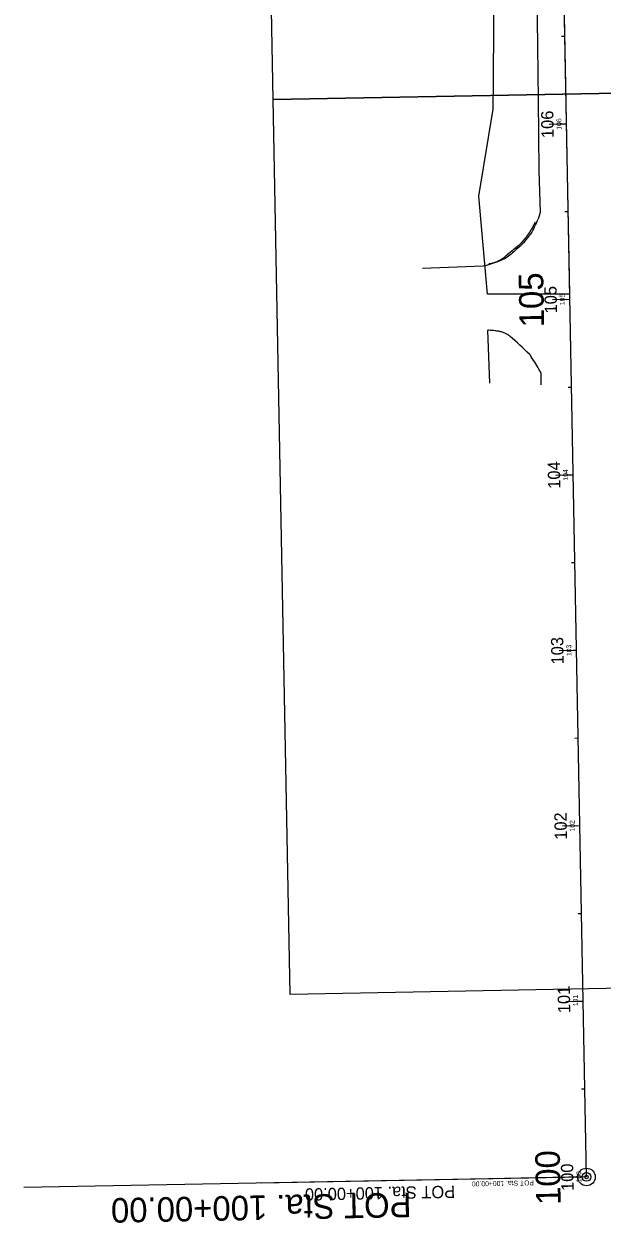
# Model space of a CAD drawing. Extents: x 2287043 to 2296348, y 637947 to 641293.
# Drawn here: x 2287081 to 2287410, y 637947 to 638630 of the extents above; entities that cross this region are included whole.
import ezdxf

# ---------------------------------------------------------------- set-up
doc = ezdxf.new("R2010")
doc.units = 0
for name, color, linetype in [('DR_P_Drainage_Area', 7, 'Continuous'), ('GE_X_CL_100', 7, 'Continuous'), ('GE_X_CL_20', 7, 'Continuous'), ('GE_X_CL_50', 7, 'Continuous'), ('SC_Scratch2', 7, 'Continuous'), ('SC_Scratch4', 7, 'Continuous')]:
    doc.layers.add(name, color=color, linetype=linetype)

msp = doc.modelspace()

# ---------------------------------------------------------------- linework, layer by layer
at = {"layer": 'DR_P_Drainage_Area'}
msp.add_line((2287391.95, 638476.45), (2287345.11, 638476.45), dxfattribs=at)
for points in [[(2287365.99, 639861.68), (2287378.81, 639153.12), (2287391.95, 638476.45)], [(2287345.11, 638476.45), (2287340.17, 638532.29), (2287348.41, 638581.77), (2287348.51, 638598.52), (2287348.89, 638659.2), (2287344.64, 638715.18), (2287332.07, 638761.85), (2287327.5, 638851.7)]]:
    msp.add_lwpolyline(points, dxfattribs=at)
at = {"layer": 'GE_X_CL_100'}
for p, q in [((2287401.6, 637973.38), (2287357.08, 640335.42)), ((2287390.29, 638573.28), (2287380.3, 638573.09)), ((2287392.18, 638473.29), (2287382.18, 638473.1)), ((2287394.06, 638373.31), (2287384.06, 638373.12)), ((2287395.95, 638273.33), (2287385.95, 638273.14)), ((2287397.83, 638173.35), (2287387.83, 638173.16)), ((2287399.72, 638073.36), (2287389.72, 638073.18)), ((2287396.6, 637973.29), (2287081.17, 637967.34)), ((2287401.6, 637973.38), (2287391.6, 637973.19))]:
    msp.add_line(p, q, dxfattribs=at)
msp.add_circle((2287401.6, 637973.38), 5, dxfattribs=at)
at = {"layer": 'GE_X_CL_20'}
for p, q in [((2287401.6, 637973.38), (2287357.08, 640335.42)), ((2287389.35, 638623.27), (2287387.35, 638623.23)), ((2287390.29, 638573.28), (2287388.29, 638573.24)), ((2287391.24, 638523.28), (2287389.24, 638523.25)), ((2287392.18, 638473.29), (2287390.18, 638473.26)), ((2287393.12, 638423.3), (2287391.12, 638423.26)), ((2287394.06, 638373.31), (2287392.06, 638373.27)), ((2287395.01, 638323.32), (2287393.01, 638323.28)), ((2287395.95, 638273.33), (2287393.95, 638273.29)), ((2287396.89, 638223.34), (2287394.89, 638223.3)), ((2287397.83, 638173.35), (2287395.83, 638173.31)), ((2287398.77, 638123.36), (2287396.77, 638123.32)), ((2287399.72, 638073.36), (2287397.72, 638073.33)), ((2287400.66, 638023.37), (2287398.66, 638023.34)), ((2287400.6, 637973.36), (2287327.52, 637971.99)), ((2287401.6, 637973.38), (2287399.6, 637973.34))]:
    msp.add_line(p, q, dxfattribs=at)
msp.add_circle((2287401.6, 637973.38), 1, dxfattribs=at)
at = {"layer": 'GE_X_CL_50'}
for p, q in [((2287401.6, 637973.38), (2287357.08, 640335.42)), ((2287390.29, 638573.28), (2287385.3, 638573.18)), ((2287390.29, 638573.28), (2287385.3, 638573.18)), ((2287392.18, 638473.29), (2287387.18, 638473.2)), ((2287392.18, 638473.29), (2287387.18, 638473.2)), ((2287394.06, 638373.31), (2287389.06, 638373.22)), ((2287394.06, 638373.31), (2287389.06, 638373.22)), ((2287395.95, 638273.33), (2287390.95, 638273.23)), ((2287395.95, 638273.33), (2287390.95, 638273.23)), ((2287397.83, 638173.35), (2287392.83, 638173.25)), ((2287397.83, 638173.35), (2287392.83, 638173.25)), ((2287399.72, 638073.36), (2287394.72, 638073.27)), ((2287399.72, 638073.36), (2287394.72, 638073.27)), ((2287399.1, 637973.33), (2287216.39, 637969.89)), ((2287399.1, 637973.33), (2287216.39, 637969.89)), ((2287401.6, 637973.38), (2287396.6, 637973.29)), ((2287401.6, 637973.38), (2287396.6, 637973.29))]:
    msp.add_line(p, q, dxfattribs=at)
msp.add_circle((2287401.6, 637973.38), 2.5, dxfattribs=at)
msp.add_circle((2287401.6, 637973.38), 2.5, dxfattribs=at)
at = {"layer": 'SC_Scratch2'}
for points in [[(2287223.14, 638587.24), (2287213.53, 639097.15), (2287543.47, 639103.37), (2287553.08, 638593.46)], [(2287232.75, 638077.33), (2287223.14, 638587.24), (2287553.08, 638593.46), (2287562.69, 638083.55)]]:
    msp.add_lwpolyline(points, close=True, dxfattribs=at)
at = {"layer": 'SC_Scratch4'}
for p, q in [((2287375.16, 638522.93), (2287373.97, 638519.1)), ((2287369.14, 638510.1), (2287365.74, 638505.65)), ((2287369.57, 638510.68), (2287369.14, 638510.1)), ((2287369.57, 638510.68), (2287369.88, 638510.55)), ((2287342.63, 638492.34), (2287308.17, 638491.1)), ((2287346.59, 638425.74), (2287345.42, 638455.81)), ((2287369.52, 638441.89), (2287369.24, 638442.1)), ((2287369.52, 638441.89), (2287370.03, 638440.47)), ((2287374.96, 638432.68), (2287375.56, 638431.4))]:
    msp.add_line(p, q, dxfattribs=at)
for points in [[(2287371.95, 638767.2), (2287373.28, 638718.62), (2287373.47, 638673.87), (2287373.54, 638632.64), (2287374, 638587.11), (2287374.45, 638546.92), (2287375.16, 638522.93)], [(2287372.28, 638517.32), (2287372.2, 638517.16), (2287372.12, 638516.99), (2287372.04, 638516.83), (2287371.96, 638516.66), (2287371.87, 638516.5), (2287371.79, 638516.33), (2287371.71, 638516.17), (2287371.62, 638516.01), (2287371.54, 638515.84), (2287371.45, 638515.68), (2287371.37, 638515.52), (2287371.28, 638515.36), (2287371.19, 638515.19), (2287371.1, 638515.03), (2287371.02, 638514.87), (2287370.93, 638514.71), (2287370.84, 638514.55), (2287370.75, 638514.39), (2287370.66, 638514.23), (2287370.56, 638514.07), (2287370.47, 638513.91), (2287370.38, 638513.75), (2287370.29, 638513.59), (2287370.19, 638513.43), (2287370.1, 638513.28), (2287370, 638513.12), (2287369.91, 638512.96), (2287369.81, 638512.8), (2287369.72, 638512.65), (2287369.62, 638512.49), (2287369.52, 638512.33), (2287369.42, 638512.18), (2287369.32, 638512.02), (2287369.22, 638511.87), (2287369.12, 638511.71), (2287369.02, 638511.56), (2287368.92, 638511.41), (2287368.82, 638511.25), (2287368.72, 638511.1), (2287368.62, 638510.95), (2287368.51, 638510.8), (2287368.41, 638510.64), (2287368.3, 638510.49), (2287368.2, 638510.34), (2287368.09, 638510.19), (2287367.99, 638510.04), (2287367.88, 638509.89), (2287367.77, 638509.74), (2287367.67, 638509.59), (2287367.56, 638509.44), (2287367.45, 638509.29), (2287367.34, 638509.15), (2287367.23, 638509), (2287367.12, 638508.85), (2287367.01, 638508.7), (2287366.9, 638508.56), (2287366.78, 638508.41), (2287366.67, 638508.27), (2287366.56, 638508.12), (2287366.45, 638507.98), (2287366.33, 638507.83), (2287366.22, 638507.69), (2287366.1, 638507.54), (2287365.99, 638507.4), (2287365.87, 638507.26), (2287365.75, 638507.12), (2287365.64, 638506.97), (2287365.52, 638506.83), (2287365.4, 638506.69), (2287365.28, 638506.55), (2287365.16, 638506.41), (2287365.04, 638506.27), (2287364.92, 638506.13), (2287364.8, 638505.99), (2287364.68, 638505.86), (2287364.56, 638505.72), (2287364.43, 638505.58), (2287364.31, 638505.44), (2287364.19, 638505.31), (2287364.06, 638505.17), (2287363.94, 638505.03), (2287363.82, 638504.9), (2287363.69, 638504.76), (2287363.56, 638504.63), (2287363.44, 638504.5), (2287363.31, 638504.36)], [(2287356.13, 638498.69), (2287355.92, 638498.48), (2287355.71, 638498.27), (2287355.49, 638498.07), (2287355.27, 638497.87), (2287355.04, 638497.67), (2287354.81, 638497.47), (2287354.58, 638497.29), (2287354.35, 638497.1), (2287354.11, 638496.92), (2287353.87, 638496.74), (2287353.62, 638496.57), (2287353.38, 638496.4), (2287353.13, 638496.23), (2287352.87, 638496.07), (2287352.62, 638495.91), (2287352.36, 638495.76), (2287352.1, 638495.61), (2287351.84, 638495.47), (2287351.57, 638495.33), (2287351.31, 638495.2), (2287351.04, 638495.07), (2287350.76, 638494.94), (2287350.49, 638494.82), (2287350.21, 638494.71), (2287349.94, 638494.6), (2287349.66, 638494.49), (2287349.37, 638494.39), (2287349.09, 638494.29), (2287348.81, 638494.2), (2287348.52, 638494.11), (2287348.23, 638494.03), (2287347.94, 638493.95), (2287347.65, 638493.88), (2287347.36, 638493.81), (2287347.07, 638493.75), (2287346.78, 638493.69), (2287346.48, 638493.64), (2287346.19, 638493.6), (2287345.89, 638493.55)], [(2287363.31, 638504.36), (2287356.13, 638498.69)], [(2287370.03, 638440.47), (2287370.03, 638440.47)], [(2287375.56, 638431.4), (2287375.5, 638424.82)]]:
    msp.add_lwpolyline(points, dxfattribs=at)
for centre, radius, start, end in [((2287285.44, 638556.13), 95.96, 331.63869, 337.29975), ((2287344.31, 638418.76), 33.66, 24.42284, 40.16881)]:
    msp.add_arc(centre, radius, start, end, dxfattribs=at)
for points in [[(2287365.74, 638505.65), (2287362.51, 638502.67), (2287356.32, 638497.47), (2287342.63, 638492.34)], [(2287369.24, 638442.1), (2287358, 638452.35), (2287357.3, 638452.92), (2287356.56, 638453.43), (2287354.97, 638454.25), (2287354.1, 638454.58), (2287353.22, 638454.86), (2287351.42, 638455.26), (2287350.48, 638455.4), (2287349.54, 638455.52), (2287347.65, 638455.7), (2287345.76, 638455.8), (2287345.42, 638455.81)]]:
    msp.add_spline(points, degree=3, dxfattribs=at)

# ---------------------------------------------------------------- texts
at = {"layer": 'GE_X_CL_100'}
for s, rotation, p in [('105', 91.07978, (2287377.47, 638457.64)), ('100', 91.07978, (2287386.9, 637957.51)), ('POT Sta. 100+00.00', 181.07978, (2287301.75, 637964.5))]:
    msp.add_text(s, height=14, rotation=rotation, dxfattribs=at).set_placement(p)
at = {"layer": 'GE_X_CL_20'}
for s, rotation, p in [('106', 91.07978, (2287387.35, 638570.13)), ('105', 91.07978, (2287389.24, 638470.16)), ('104', 91.07978, (2287391.12, 638370.21)), ('103', 91.07978, (2287393.01, 638270.19)), ('102', 91.07978, (2287394.89, 638170.24)), ('101', 91.07978, (2287396.77, 638070.72)), ('100', 91.07978, (2287398.66, 637970.21)), ('POT Sta. 100+00.00', 181.07978, (2287371.63, 637971.42))]:
    msp.add_text(s, height=2.8, rotation=rotation, dxfattribs=at).set_placement(p)
at = {"layer": 'GE_X_CL_50'}
for s, rotation, p in [('106', 91.07978, (2287382.94, 638565.42)), ('106', 91.07978, (2287382.94, 638565.42)), ('105', 91.07978, (2287384.82, 638465.47)), ('105', 91.07978, (2287384.82, 638465.47)), ('104', 91.07978, (2287386.71, 638365.57)), ('104', 91.07978, (2287386.71, 638365.57)), ('103', 91.07978, (2287388.59, 638265.47)), ('103', 91.07978, (2287388.59, 638265.47)), ('102', 91.07978, (2287390.48, 638165.58)), ('102', 91.07978, (2287390.48, 638165.58)), ('101', 91.07978, (2287392.34, 638066.75)), ('101', 91.07978, (2287392.34, 638066.75)), ('100', 91.07978, (2287394.25, 637965.45)), ('100', 91.07978, (2287394.25, 637965.45)), ('POT Sta. 100+00.00', 181.07978, (2287326.68, 637968.47)), ('POT Sta. 100+00.00', 181.07978, (2287326.68, 637968.47))]:
    msp.add_text(s, height=7, rotation=rotation, dxfattribs=at).set_placement(p)

doc.saveas('drawing.dxf')
